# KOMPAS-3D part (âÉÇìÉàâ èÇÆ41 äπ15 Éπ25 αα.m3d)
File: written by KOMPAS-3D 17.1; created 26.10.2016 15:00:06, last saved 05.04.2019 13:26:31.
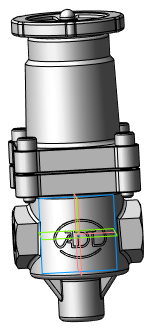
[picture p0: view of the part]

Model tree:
1. Операция без истории:3  (labels: Сталь 20  ГОСТ 1050-88)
